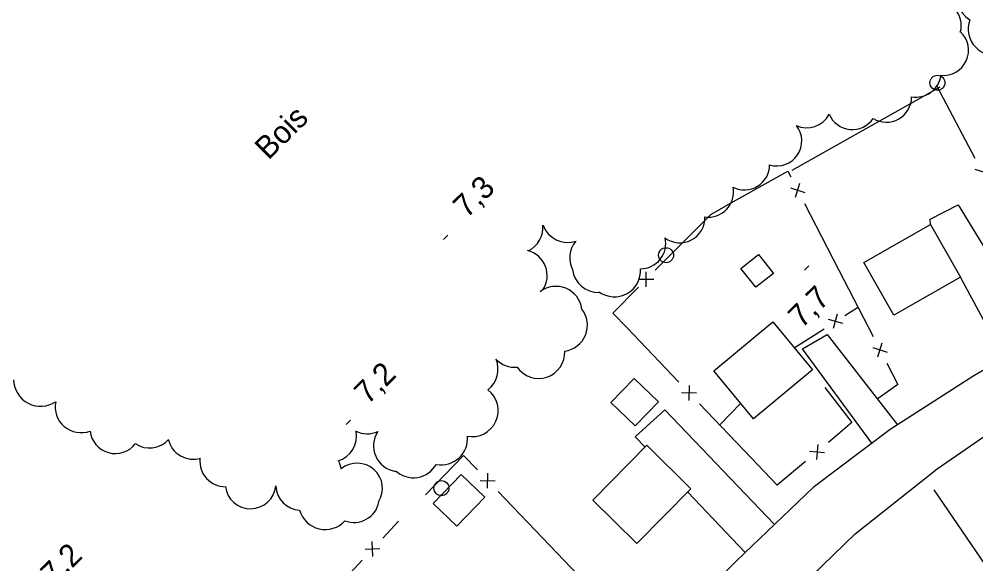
# Model space of a CAD drawing. Extents: x 381879 to 384696, y 5564785 to 5567594.
# Drawn here: x 382841.1 to 382968.9, y 5565788.8 to 5565861.6 of the extents above; entities that cross this region are included whole.
import ezdxf

# ---------------------------------------------------------------- set-up
doc = ezdxf.new("R2010")
doc.units = 0
for name, color, linetype in [('Niveau 19', 7, 'Continuous'), ('Niveau 21', 7, 'Continuous'), ('Niveau 3', 7, 'Continuous'), ('Niveau 31', 7, 'Continuous'), ('Niveau 36', 7, 'Continuous'), ('Niveau 37', 7, 'Continuous'), ('Niveau 41', 7, 'Continuous'), ('Niveau 44', 7, 'Continuous')]:
    doc.layers.add(name, color=color, linetype=linetype)

msp = doc.modelspace()

# ---------------------------------------------------------------- linework, layer by layer
at = {"layer": 'Niveau 19'}
for points in [[(382962.86, 5565834.15), (382962.83, 5565834.87), (382966.57, 5565836.77), (382977.41, 5565819.01)], [(382972.7, 5565816.27), (382972.7, 5565816.28), (382966.88, 5565827.09)], [(382955.01, 5565804.91), (382955.01, 5565804.91), (382945.77, 5565817.51), (382949.05, 5565819.45), (382958.43, 5565807.37)], [(382924.72, 5565804.41), (382923.41, 5565805.79), (382927.39, 5565809.39), (382942, 5565794.06)], [(382938.08, 5565790.31), (382930.42, 5565798.39)]]:
    msp.add_lwpolyline(points, dxfattribs=at)
at = {"layer": 'Niveau 21'}
for points in [[(383064.1, 5565858.11), (383048.13, 5565853.66), (383037.45, 5565850.22), (383025.4, 5565844.77), (383013.84, 5565839.23), (383000.34, 5565832), (382984.28, 5565823), (382968.65, 5565813.92), (382957.48, 5565806.76), (382947.18, 5565799.02), (382936.93, 5565789.21), (382925.34, 5565777.61), (382909.05, 5565761.18), (382902.96, 5565755.38)], [(382914.61, 5565754.3), (382936.73, 5565777.21), (382952.8, 5565792.82), (382963.76, 5565801.52), (382976.97, 5565810.61), (383000.04, 5565824), (383016.43, 5565833.11), (383031.77, 5565840.06), (383045.77, 5565844.63), (383055.95, 5565847.35), (383061.35, 5565847.84), (383065.37, 5565846.21), (383068.45, 5565843.53), (383070.89, 5565839.89)]]:
    msp.add_lwpolyline(points, dxfattribs=at)
at = {"layer": 'Niveau 3'}
for p, q in [((382897.8, 5565832.14), (382898.37, 5565832.71)), ((382946.04, 5565828.03), (382946.61, 5565828.6)), ((382884.82, 5565807.44), (382885.39, 5565808.01))]:
    msp.add_line(p, q, dxfattribs=at)
at = {"layer": 'Niveau 31'}
for points in [[(382966.88, 5565827.09), (382957.97, 5565822.02), (382953.95, 5565829.08), (382962.86, 5565834.15)], [(382939.52, 5565825.75), (382937.53, 5565828.28), (382939.88, 5565830.13), (382941.87, 5565827.6)], [(382947.1, 5565814.71), (382939.23, 5565808.19), (382933.92, 5565814.61), (382941.79, 5565821.12)], [(382923.42, 5565807.23), (382920.17, 5565810.35), (382923.27, 5565813.58), (382926.52, 5565810.46)], [(382930.86, 5565798.84), (382923.64, 5565791.51), (382917.74, 5565797.32), (382924.96, 5565804.65)], [(382903.32, 5565797.7), (382899.57, 5565793.83), (382896.43, 5565796.87), (382900.18, 5565800.74)]]:
    msp.add_lwpolyline(points, close=True, dxfattribs=at)
at = {"layer": 'Niveau 36'}
for centre in [(382963.78, 5565853.07), (382927.53, 5565830.04), (382897.53, 5565798.92)]:
    msp.add_circle(centre, 1, dxfattribs=at)
at = {"layer": 'Niveau 37'}
for p, q in [((382970.71, 5565840.9), (382968.8, 5565841.49)), ((382944.16, 5565839.03), (382946.07, 5565838.42)), ((382944.81, 5565837.77), (382945.42, 5565839.68)), ((382924.88, 5565825.8), (382924.87, 5565827.8)), ((382925.88, 5565826.8), (382923.87, 5565826.8)), ((382949.17, 5565821.49), (382951.09, 5565820.94)), ((382950.41, 5565822.18), (382949.85, 5565820.25)), ((382955.15, 5565817.7), (382957.06, 5565817.09)), ((382955.8, 5565816.44), (382956.41, 5565818.34)), ((382930.63, 5565812.64), (382930.58, 5565810.64)), ((382931.61, 5565811.62), (382929.6, 5565811.67)), ((382947.79, 5565804.76), (382947.61, 5565802.76)), ((382946.7, 5565803.85), (382948.7, 5565803.67)), ((382903.69, 5565798.93), (382903.74, 5565800.93)), ((382902.71, 5565799.95), (382904.72, 5565799.9)), ((382888.36, 5565789.78), (382888.28, 5565791.78)), ((382889.32, 5565790.82), (382887.32, 5565790.74))]:
    msp.add_line(p, q, dxfattribs=at)
for points in [[(382964.16, 5565851.81), (382963.69, 5565852.71)], [(382968.82, 5565842.96), (382964.16, 5565851.81)], [(382935.85, 5565836.79), (382943.8, 5565841.28), (382944.2, 5565840.5)], [(382926.1, 5565828.03), (382933.52, 5565835.48), (382935.85, 5565836.79)], [(382946.03, 5565836.95), (382950.61, 5565828.06)], [(382950.61, 5565828.06), (382955.19, 5565819.17)], [(382922.32, 5565820.32), (382920.42, 5565822.31), (382923.87, 5565825.78)], [(382951.42, 5565821.97), (382953.09, 5565823.03)], [(382929.22, 5565813.09), (382922.32, 5565820.32)], [(382944.65, 5565817.66), (382948.64, 5565820.2)], [(382957.02, 5565815.61), (382958.48, 5565812.78), (382955.87, 5565810.88)], [(382948.74, 5565812.35), (382952.36, 5565807.67), (382949.23, 5565805.04)], [(382938.89, 5565802.96), (382931.99, 5565810.2)], [(382934.7, 5565807.36), (382937.51, 5565810.27)], [(382895.39, 5565798.03), (382900.49, 5565803.3), (382902.33, 5565801.37)], [(382946.17, 5565802.47), (382942.39, 5565799.3), (382938.89, 5565802.96)], [(382905.1, 5565798.48), (382912.01, 5565791.25)], [(382889.68, 5565792.25), (382891.78, 5565794.52)], [(382912.01, 5565791.25), (382916.72, 5565786.33)], [(382882.86, 5565781.89), (382881.56, 5565783.48), (382886.96, 5565789.31)]]:
    msp.add_lwpolyline(points, dxfattribs=at)
at = {"layer": 'Niveau 41'}
for points in [[(382944.36, 5565841.41), (382964.15, 5565852.52)], [(382963.3, 5565798.68), (382980.07, 5565774.13), (383042.17, 5565805.84)]]:
    msp.add_lwpolyline(points, dxfattribs=at)
at = {"layer": 'Niveau 44'}
for centre, radius, start, end in [((382969.9, 5565864.49), 3.5, 153.542, 239.218), ((382971.4, 5565860.27), 3.51, 159.7585, 289.0767), ((382901.6, 5565814.83), 3.49, 307.3704, 22.5143), ((382882, 5565796.95), 3.56, 195.7934, 317.8729)]:
    msp.add_arc(centre, radius, start, end, dxfattribs=at)
for centre, major_axis, ratio, start_param, end_param in [((382963.61, 5565860.74), (-2.71, 1.98), 0.999984, 3.496697, 5.554033), ((382964.58, 5565857.41), (0.62, 3.3), 0.999856, 3.222043, 5.7149), ((382960.94, 5565854.5), (2.08, 2.62), 0.999857, 3.631171, 5.256094), ((382956.95, 5565851.18), (1.27, -3.13), 0.999753, 5.351485, 7.474172), ((382946.33, 5565850.43), (1.21, -3.14), 0.999896, 5.485447, 7.00298), ((382952.42, 5565850.22), (-0.34, -3.37), 0.999909, 5.223432, 7.348254), ((382942.31, 5565845.31), (2.8, 1.85), 0.999776, 3.843531, 6.366546), ((382938, 5565842.12), (2.67, 2.05), 0.999856, 3.591412, 5.62238), ((382933.19, 5565838.48), (2.5, 2.24), 0.999855, 3.837887, 5.741645), ((382907.63, 5565833.77), (1.71, 3.04), 0.994764, 4.100873, 5.308278), ((382914.39, 5565835.21), (3.34, -1.02), 0.994903, 3.77644, 5.336775), ((382929.37, 5565835.05), (0.34, -3.34), 0.997757, 5.548621, 7.784035), ((382918.14, 5565829.68), (1.39, -3.2), 0.995032, 3.629876, 4.771993), ((382924.14, 5565831.59), (1.64, 2.93), 0.999856, 3.642989, 5.453126), ((382908.17, 5565827.3), (3.48, 0.01), 0.995533, 5.699793, 7.59823), ((382918.48, 5565828.54), (2.32, -2.6), 0.997081, 4.110029, 5.579075), ((382920.65, 5565827.94), (2.85, 1.99), 0.995711, 3.46156, 5.75355), ((382912.83, 5565822.4), (-3.18, 1.42), 0.99851, 3.690078, 5.789432), ((382913.55, 5565820.68), (1.05, 3.32), 0.997858, 3.575317, 5.691541), ((382907.35, 5565818.54), (3.01, -1.75), 0.997848, 4.418724, 5.321833), ((382910.52, 5565817.04), (2.91, 1.91), 0.996199, 3.160511, 5.753211), ((382844, 5565813.47), (-1.94, -3.05), 0.999545, 5.305595, 7.435498), ((382901.62, 5565809.29), (1.94, 2.9), 0.998197, 3.535498, 6.223979), ((382849.38, 5565809.78), (-2.6, -2.26), 0.99983, 5.368974, 7.496149), ((382853.93, 5565806.85), (3.11, -1.29), 0.98047, 3.632899, 6.032848), ((382882.72, 5565805.87), (2.4, 2.52), 0.995198, 4.19683, 5.676636), ((382887.63, 5565809.66), (2.42, 2.51), 0.993876, 3.451843, 4.320924), ((382891.95, 5565804.6), (1.99, -2.87), 0.998197, 3.535498, 5.509282), ((382897.53, 5565805.51), (2.75, 2.14), 0.996624, 3.853432, 5.725636), ((382858.54, 5565807.62), (3.33, 0.5), 0.991579, 3.961128, 5.412063), ((382864.31, 5565806.13), (2.42, -2.35), 0.984654, 4.129814, 5.789776), ((382868.62, 5565802.44), (2.78, -1.92), 0.982551, 3.635602, 5.326412), ((382880.85, 5565800.98), (-1.87, 2.81), 0.987512, 4.267949, 4.618159), ((382886.29, 5565798.92), (-3.25, 0.92), 0.983666, 2.839313, 5.676619), ((382893.78, 5565803.76), (3.47, -0.04), 0.994642, 3.965685, 5.805878), ((382872.03, 5565799.53), (2.98, 1.61), 0.993588, 2.763311, 5.692838), ((382878.74, 5565799.34), (1.44, -3.05), 0.990829, 4.31468, 5.790002), ((382885.87, 5565797.7), (2.57, 2.19), 0.994255, 3.635166, 5.388229)]:
    msp.add_ellipse(centre, major_axis=major_axis, ratio=ratio, start_param=start_param, end_param=end_param, dxfattribs=at)

# ---------------------------------------------------------------- texts
at = {"layer": 'Niveau 3'}
for s, p in [('7,3  ', (382900.91, 5565834.88)), ('7,7', (382945.66, 5565820.16)), ('7,2', (382887.7, 5565809.98)), ('7,2', (382845.8, 5565785.79))]:
    msp.add_text(s, height=3, rotation=44.7717, dxfattribs=at).set_placement(p)
at = {"layer": 'Niveau 44'}
msp.add_text('Bois', height=3, rotation=44.7707, dxfattribs=at).set_placement((382874.41, 5565842.66))

doc.saveas('drawing.dxf')
